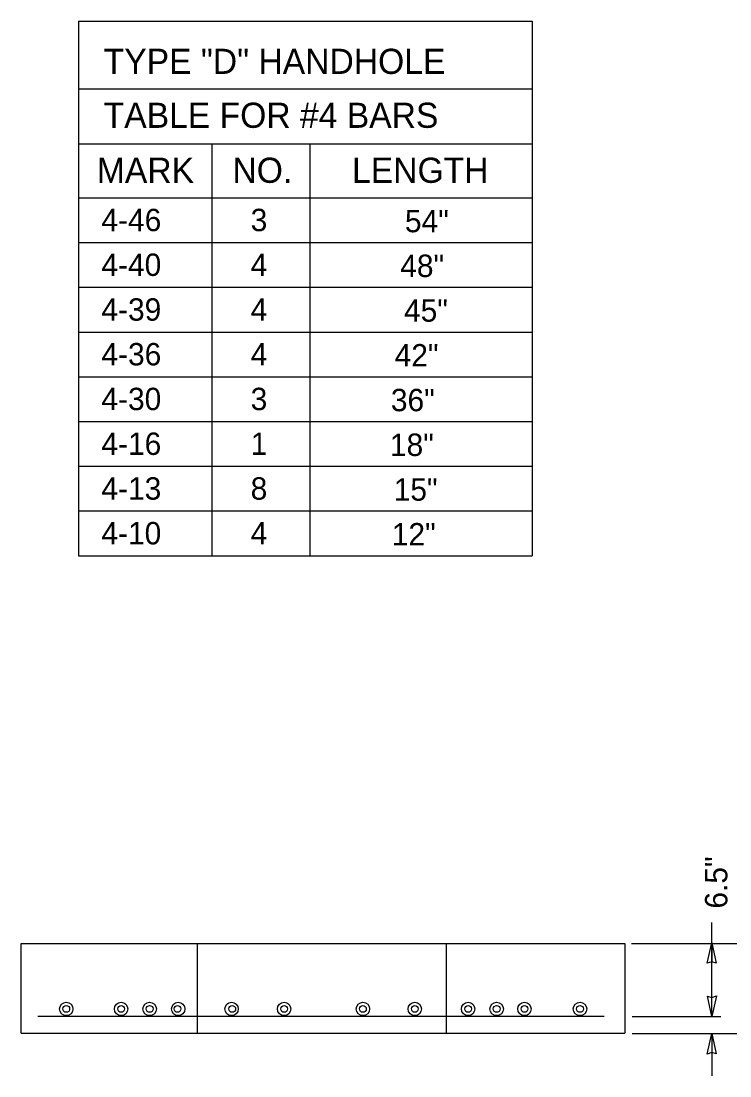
# Model space of a CAD drawing. Extents: x 19188 to 19495, y 20866 to 21061.
# Drawn here: x 19292.36 to 19318.92, y 21013.7 to 21053.2 of the extents above; entities that cross this region are included whole.
import ezdxf

# ---------------------------------------------------------------- set-up
doc = ezdxf.new("R2010")
doc.units = 0
doc.layers.add('G-ANNO-NOTE', color=7, linetype='Continuous')

msp = doc.modelspace()

# ---------------------------------------------------------------- linework, layer by layer
at = {"layer": 'G-ANNO-NOTE'}
for p, q in [((19294.516, 21053.202), (19311.505, 21053.202)), ((19294.516, 21053.202), (19294.516, 21033.179)), ((19311.505, 21053.202), (19311.505, 21033.179)), ((19294.516, 21050.666), (19311.505, 21050.666)), ((19294.516, 21048.605), (19311.505, 21048.605)), ((19299.51, 21048.605), (19299.51, 21033.179)), ((19303.181, 21048.605), (19303.181, 21033.179)), ((19294.516, 21046.585), (19311.505, 21046.585)), ((19294.516, 21044.909), (19311.505, 21044.909)), ((19294.516, 21043.233), (19311.505, 21043.233)), ((19294.516, 21041.557), (19311.505, 21041.557)), ((19294.516, 21039.882), (19311.505, 21039.882)), ((19294.516, 21038.206), (19311.505, 21038.206)), ((19294.516, 21036.53), (19311.505, 21036.53)), ((19294.516, 21034.855), (19311.505, 21034.855)), ((19294.516, 21033.179), (19311.505, 21033.179)), ((19318.238, 21015.918), (19318.238, 21019.442)), ((19292.361, 21018.652), (19314.983, 21018.652)), ((19292.361, 21015.3), (19292.361, 21018.652)), ((19298.972, 21015.3), (19298.972, 21018.652)), ((19308.293, 21015.3), (19308.293, 21018.652)), ((19314.983, 21018.652), (19314.983, 21015.3)), ((19315.227, 21018.661), (19321.418, 21018.661)), ((19318.238, 21018.687), (19318.238, 21017.976)), ((19318.238, 21015.918), (19318.238, 21016.629)), ((19292.994, 21015.929), (19314.199, 21015.929)), ((19315.256, 21015.918), (19318.576, 21015.918)), ((19292.361, 21015.3), (19314.983, 21015.3)), ((19315.256, 21015.291), (19321.418, 21015.291)), ((19318.238, 21015.291), (19318.238, 21013.698)), ((19318.238, 21015.291), (19318.238, 21014.581))]:
    msp.add_line(p, q, dxfattribs=at)
for points in [[(19318.238, 21017.976), (19318.068, 21017.914), (19318.238, 21018.687), (19318.4, 21017.915), (19318.238, 21017.976)], [(19318.238, 21016.629), (19318.408, 21016.691), (19318.238, 21015.918), (19318.076, 21016.69), (19318.238, 21016.629)], [(19318.238, 21014.58), (19318.068, 21014.518), (19318.238, 21015.291), (19318.4, 21014.52), (19318.238, 21014.58)]]:
    msp.add_lwpolyline(points, dxfattribs=at)
for centre, radius in [((19294.054, 21016.205), 0.251), ((19296.108, 21016.205), 0.251), ((19297.177, 21016.205), 0.251), ((19298.246, 21016.205), 0.251), ((19300.244, 21016.205), 0.251), ((19302.214, 21016.205), 0.251), ((19305.168, 21016.205), 0.251), ((19307.11, 21016.205), 0.251), ((19309.108, 21016.205), 0.251), ((19310.177, 21016.205), 0.251), ((19311.218, 21016.205), 0.251), ((19313.3, 21016.205), 0.251), ((19294.054, 21016.205), 0.126), ((19296.108, 21016.205), 0.126), ((19297.177, 21016.205), 0.126), ((19298.218, 21016.205), 0.126), ((19300.272, 21016.205), 0.126), ((19302.214, 21016.205), 0.126), ((19305.168, 21016.205), 0.126), ((19307.11, 21016.205), 0.126), ((19309.108, 21016.205), 0.126), ((19310.177, 21016.205), 0.126), ((19311.218, 21016.205), 0.126), ((19313.3, 21016.205), 0.126)]:
    msp.add_circle(centre, radius, dxfattribs=at)

# ---------------------------------------------------------------- texts
for s, height, p in [('TYPE "D" HANDHOLE', 0.94259, (19295.455, 21051.224)), ('TABLE FOR #4 BARS', 0.94259, (19295.455, 21049.204)), ('MARK', 0.9426, (19295.199, 21047.144)), ('NO.', 0.9426, (19300.278, 21047.144)), ('LENGTH', 0.9426, (19304.76, 21047.144)), ('4-46', 0.8379, (19295.37, 21045.334)), ('3', 0.838, (19300.961, 21045.334)), ('54"', 0.8379, (19306.741, 21045.294)), ('4-40', 0.8379, (19295.37, 21043.658)), ('4', 0.838, (19300.961, 21043.658)), ('48"', 0.8379, (19306.565, 21043.618)), ('4-39', 0.8379, (19295.37, 21041.982)), ('4', 0.838, (19300.961, 21041.982)), ('45"', 0.8379, (19306.706, 21041.943)), ('4-36', 0.8379, (19295.37, 21040.307)), ('4', 0.838, (19300.961, 21040.307)), ('42"', 0.8379, (19306.355, 21040.267)), ('4-30', 0.8379, (19295.37, 21038.631)), ('3', 0.838, (19300.961, 21038.631)), ('36"', 0.8379, (19306.214, 21038.591)), ('4-16', 0.8379, (19295.37, 21036.955)), ('1', 0.838, (19300.961, 21036.955)), ('18"', 0.8379, (19306.179, 21036.916)), ('4-13', 0.8379, (19295.37, 21035.279)), ('8', 0.838, (19300.961, 21035.279)), ('15"', 0.8379, (19306.32, 21035.24)), ('4-10', 0.8379, (19295.37, 21033.604)), ('4', 0.838, (19300.961, 21033.604)), ('12"', 0.8379, (19306.249, 21033.564))]:
    msp.add_text(s, height=height, dxfattribs=at).set_placement(p)
msp.add_text('6.5"', height=0.8379, rotation=90, dxfattribs=at).set_placement((19318.82, 21019.963))

doc.saveas('drawing.dxf')
